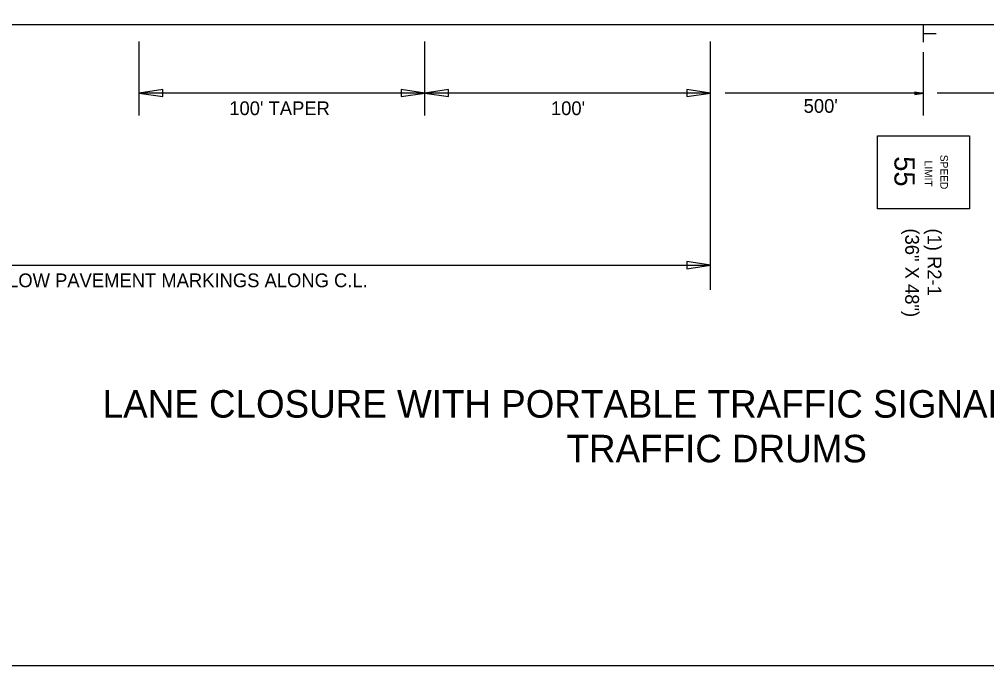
# Model space of a CAD drawing. Extents: x 1806907 to 1812607, y 675071 to 676228.
# Drawn here: x 1809449.2 to 1809871.3, y 675071.2 to 675353.3 of the extents above; entities that cross this region are included whole.
import ezdxf

# ---------------------------------------------------------------- set-up
doc = ezdxf.new("R2010")
doc.units = 0
doc.layers.add('Default', color=7, linetype='Continuous')
doc.layers.add('DSN_DRFT_Named-Boundary', color=7, linetype='Continuous')

msp = doc.modelspace()

# ---------------------------------------------------------------- linework, layer by layer
at = {"layer": 'Default'}
for p, q in [((1809377.42, 675351.1), (1810285.94, 675351.1)), ((1809843.73, 675343.27), (1809843.73, 675351.1)), ((1809843.84, 675347.16), (1809849.18, 675347.16)), ((1809501.54, 675311.31), (1809501.54, 675343.65)), ((1809626.17, 675311.31), (1809626.17, 675343.65)), ((1809750.78, 675235.2), (1809750.78, 675343.65)), ((1809843.73, 675311.31), (1809843.73, 675338.92)), ((1809511.84, 675322.64), (1809501.54, 675321.1)), ((1809501.54, 675321.1), (1809511.84, 675319.55)), ((1809626.17, 675321.1), (1809501.54, 675321.1)), ((1809511.84, 675319.55), (1809511.84, 675322.64)), ((1809626.17, 675321.1), (1809615.87, 675322.64)), ((1809615.87, 675322.64), (1809615.87, 675319.55)), ((1809615.87, 675319.55), (1809626.17, 675321.1)), ((1809636.48, 675322.64), (1809626.17, 675321.1)), ((1809626.17, 675321.1), (1809636.48, 675319.55)), ((1809750.78, 675321.1), (1809626.17, 675321.1)), ((1809636.48, 675319.55), (1809636.48, 675322.64)), ((1809750.81, 675321.1), (1809740.5, 675322.64)), ((1809740.5, 675322.64), (1809740.5, 675319.55)), ((1809740.5, 675319.55), (1809750.81, 675321.1)), ((1809843.73, 675321.1), (1809757.17, 675321.1)), ((1809839.98, 675321.66), (1809843.73, 675321.1)), ((1809839.98, 675321.66), (1809839.98, 675320.54)), ((1809839.98, 675321.57), (1809843.1, 675321.1)), ((1809839.98, 675321.47), (1809842.46, 675321.1)), ((1809839.98, 675321.38), (1809841.83, 675321.1)), ((1809839.98, 675321.28), (1809841.2, 675321.1)), ((1809839.98, 675321.19), (1809840.57, 675321.1)), ((1809839.98, 675320.54), (1809843.73, 675321.1)), ((1809839.98, 675320.91), (1809841.2, 675321.1)), ((1809839.98, 675320.72), (1809842.46, 675321.1)), ((1809839.98, 675320.63), (1809843.1, 675321.1)), ((1809839.98, 675320.82), (1809841.83, 675321.1)), ((1809839.98, 675321.01), (1809840.57, 675321.1)), ((1809940.38, 675321.1), (1809849.64, 675321.1)), ((1809227.42, 675245.99), (1809750.78, 675245.99)), ((1809750.78, 675245.99), (1809740.48, 675247.53)), ((1809740.48, 675247.53), (1809740.48, 675244.44)), ((1809740.48, 675244.44), (1809750.78, 675245.99))]:
    msp.add_line(p, q, dxfattribs=at)
msp.add_lwpolyline([(1809863.81, 675270.57), (1809823.64, 675270.57), (1809823.64, 675302.45), (1809863.81, 675302.45)], close=True, dxfattribs=at)
at = {"layer": 'DSN_DRFT_Named-Boundary'}
msp.add_lwpolyline([(1808931.68, 675071.2), (1810581.68, 675071.2), (1810581.68, 676070.26), (1808931.68, 676070.26)], close=True, dxfattribs=at)

# ---------------------------------------------------------------- texts
at = {"layer": 'Default'}
for s, height, p in [("100' TAPER", 6, (1809540.82, 675311.49)), ("100'", 6, (1809681.16, 675311.49)), ("500'", 6, (1809791.43, 675312.49)), ('REMOVE EXISTING YELLOW PAVEMENT MARKINGS ALONG C.L.', 6, (1809352.47, 675236.37)), ('LANE CLOSURE WITH PORTABLE TRAFFIC SIGNAL SYSTEM &', 12, (1809485.6, 675179.45)), ('TRAFFIC DRUMS', 12, (1809687.99, 675159.95))]:
    msp.add_text(s, height=height, dxfattribs=at).set_placement(p)
for s, height, p in [('55', 8.897, (1809831.04, 675293.54)), ('LIMIT', 3.32, (1809844.21, 675291.61)), ('SPEED', 3.32, (1809851.07, 675294.15)), ('(36" X 48")', 6, (1809835.76, 675262.02)), ('(1) R2-1', 6, (1809845.54, 675262.02))]:
    msp.add_text(s, height=height, rotation=270, dxfattribs=at).set_placement(p)

doc.saveas('drawing.dxf')
